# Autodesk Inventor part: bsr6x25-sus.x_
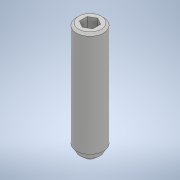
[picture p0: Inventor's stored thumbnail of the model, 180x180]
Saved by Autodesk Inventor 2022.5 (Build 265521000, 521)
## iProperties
Created: 2020-01
Part Number: bsr6x25-sus.x_
Material: 一般
Document SubType Name: Modeling
Designer: ImaoCorp
Density: 1 g/cm^3
Appearance: 既定
Sending System: SOLIDWORKS 2018-2018316
MC: AMD64
MC_MODEL: Intel64 Family 6 Model 60 Stepping 3, GenuineIntel
OS: Windows_NT
FRU: Parasolid Version 30.0, build 310,  6- 8-2018
FORMAT: text
GUISE: transmit
KEY: bsr6x25-sus
FILE: bsr6x25-sus.x_t
DATE: Thu Jan 23 16:47:02 2020
Author: ImaoCorp
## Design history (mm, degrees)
feature "Base1"
node "ソリッド1"
